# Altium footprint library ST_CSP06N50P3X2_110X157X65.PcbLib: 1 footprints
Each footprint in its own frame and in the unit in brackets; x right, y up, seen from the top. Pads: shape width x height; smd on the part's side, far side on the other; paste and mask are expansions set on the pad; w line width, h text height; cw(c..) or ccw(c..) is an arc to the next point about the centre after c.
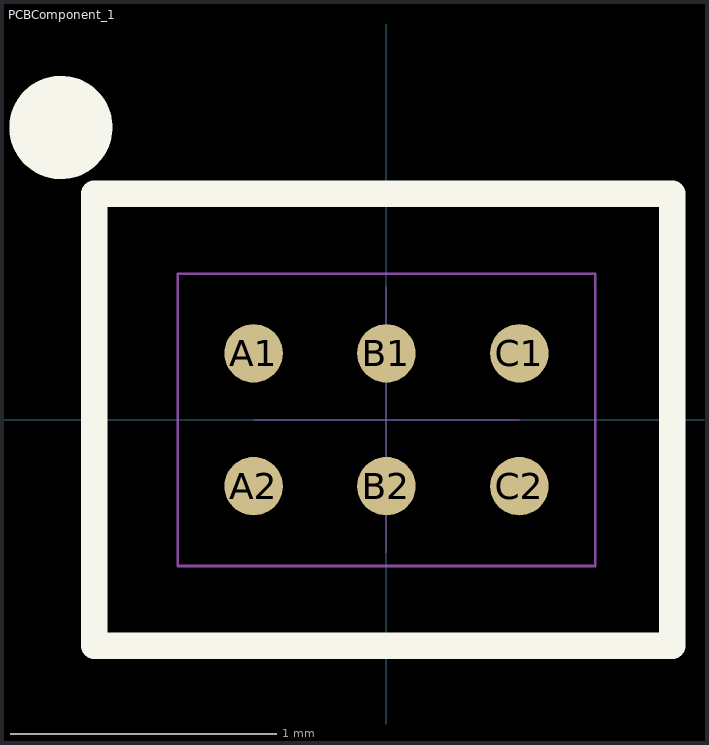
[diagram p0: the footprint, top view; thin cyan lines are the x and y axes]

## PCBComponent_1 [mm]
pads (6):
  round 0.22 smd paste-20 mask+0.04: A1(-0.5,0.25) A2(-0.5,-0.25) B1(0,0.25) B2(0,-0.25) C1(0.5,0.25) C2(0.5,-0.25)
Top Overlay:
  circle w0.2: c-1.225,1.1 r0.094
  lines w0.1: -1.1,-0.85 -1.1,0.85 1.075,0.85 1.075,-0.85 -1.1,-0.85
Top Paste:
  rectangle: 0.335,-0.415 0.665,-0.085
  rectangle: -0.165,-0.415 0.165,-0.085
  rectangle: -0.665,-0.415 -0.335,-0.085
  rectangle: 0.335,0.085 0.665,0.415
  rectangle: -0.165,0.085 0.165,0.415
  rectangle: -0.665,0.085 -0.335,0.415
Mechanical 15:
  lines w0.001: -0.5,0 0.5,0 ; 0,-0.5 0,0.5
  lines w0.01: -0.785,-0.55 -0.785,0.55 0.785,0.55 0.785,-0.55 -0.785,-0.55
3D body: height 0.65, standoff 0, extent -0.785,-0.55 0.785,0.55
